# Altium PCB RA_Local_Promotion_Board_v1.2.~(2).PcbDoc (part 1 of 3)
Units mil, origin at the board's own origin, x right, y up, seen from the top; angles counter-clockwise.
Board outline 3390.27 x 5338.61 mil, 4 copper layers (Top Layer, Signal Layer 1, Signal Layer 2, Bottom Layer), stack 30.635 mil thick; 143 components, 181 nets, 726 pads, 394 vias.
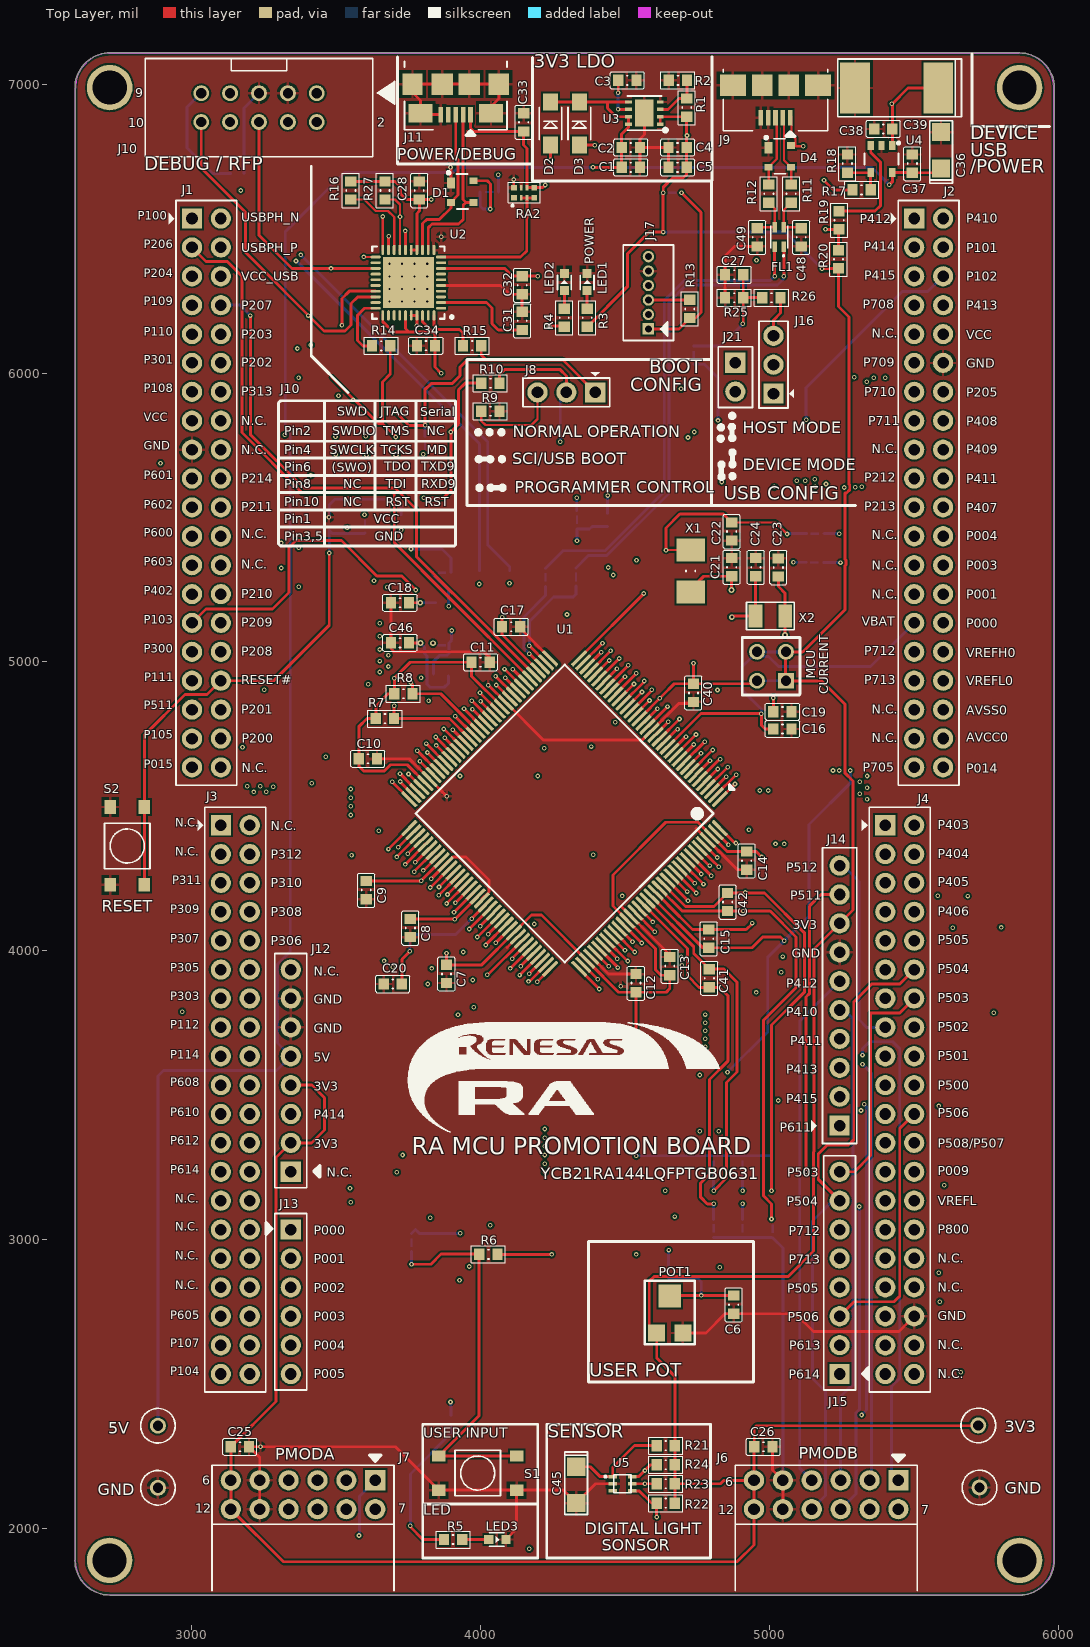
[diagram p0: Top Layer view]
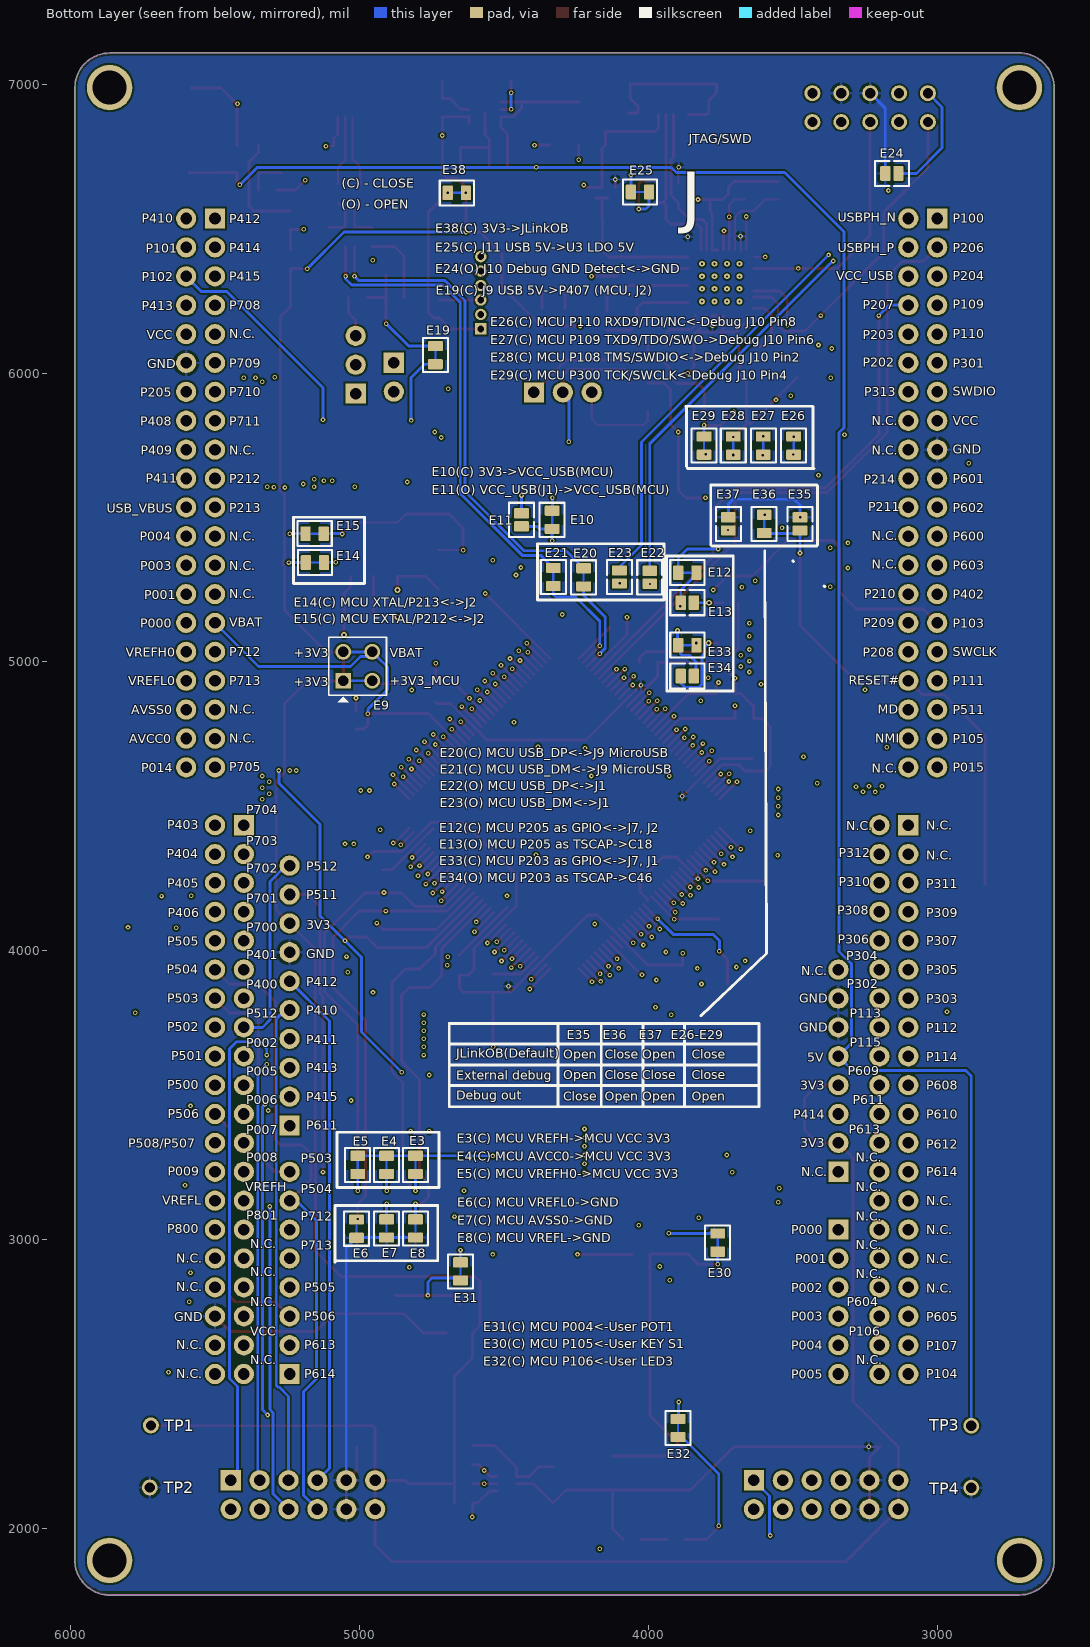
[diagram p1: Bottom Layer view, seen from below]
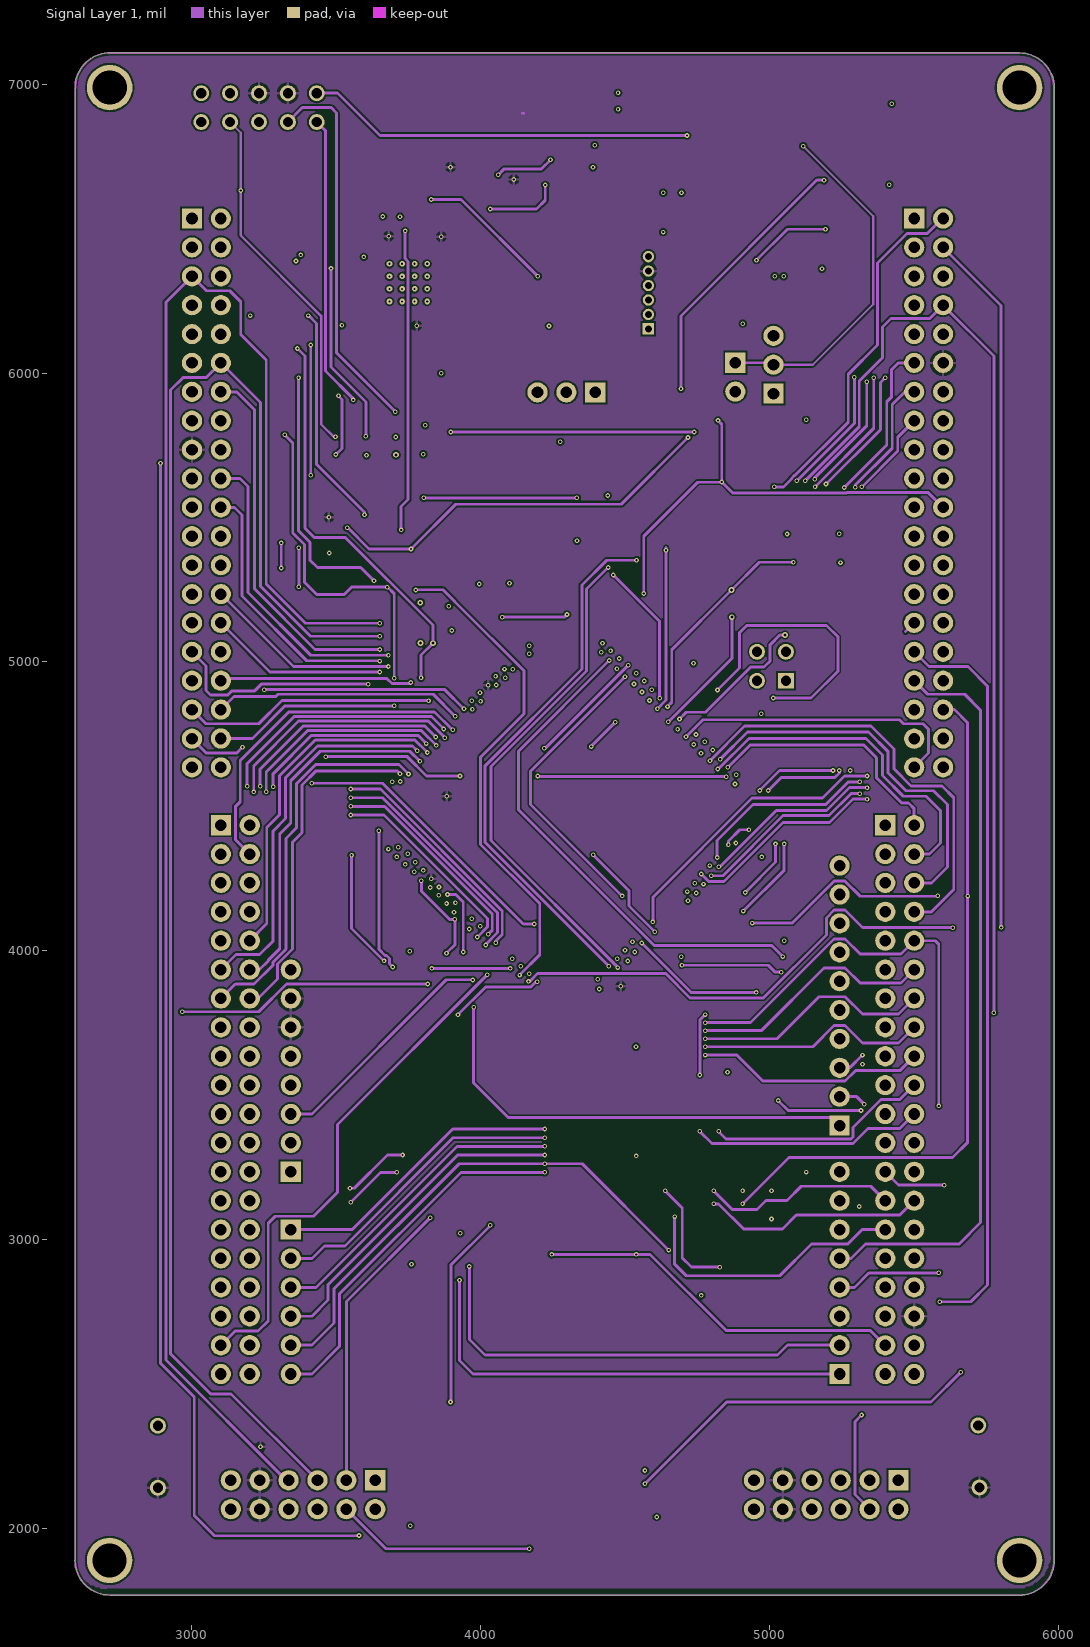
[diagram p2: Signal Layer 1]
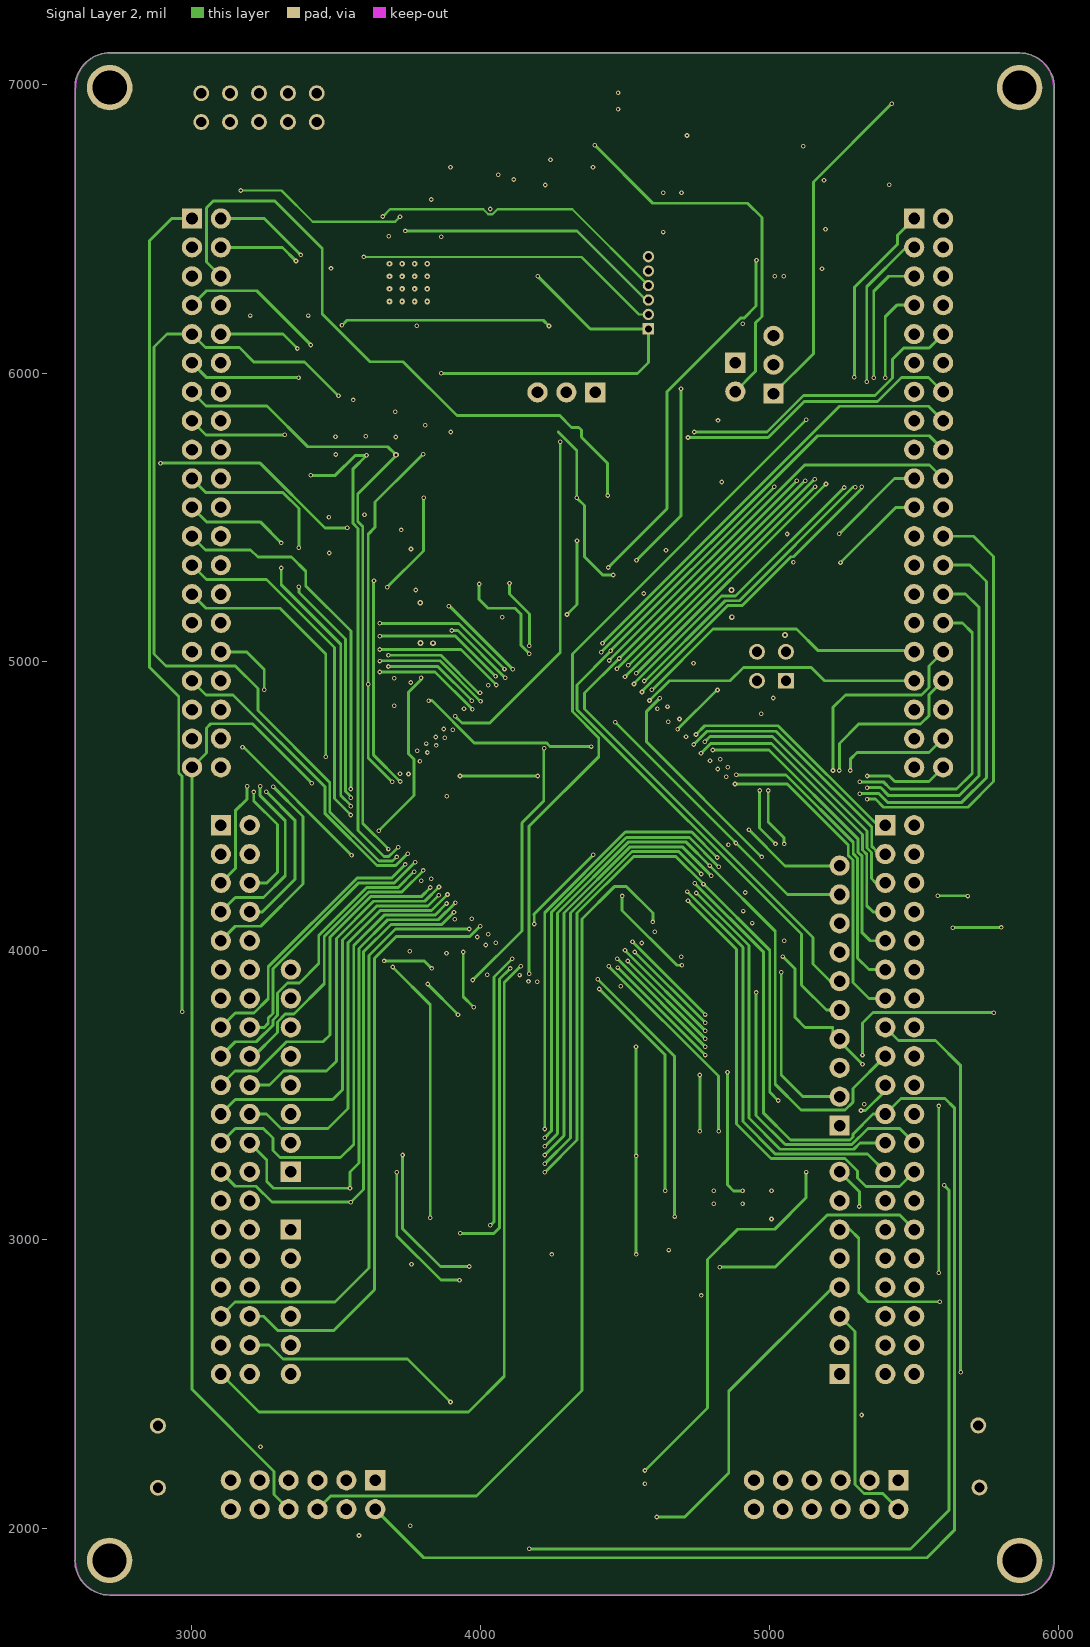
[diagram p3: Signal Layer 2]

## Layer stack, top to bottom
Top Solder: solder mask 0.4, Solder Resist, Dk 3.5
Top Layer: signal copper 1.4
Dielectric1: core 10, FR-4, Dk 4.2
Signal Layer 1: signal copper 1.4173
Dielectric2: prepreg 5, Dk 4.2
Signal Layer 2: signal copper 1.4173
Dielectric3: core 10, Dk 4.2
Bottom Layer: signal copper 1.4
Bottom Solder: solder mask 0.4, Solder Resist, Dk 3.5

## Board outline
2594.72,1889.76 cw(c2596.7,1889.76) 2595.1,1890.94 2595.1,6995.09 cw(c2597.09,6995.09) 2595.36,6996.07 cw(c2715.2,6988.19) 2707.32,7108.02 cw(c2708.3,7106.3) 2708.3,7108.28 5864.8,7108.28 cw(c5864.8,6988.19) 5984.9,6988.69 cw(c5983,6988.1) 5984.98,6988.1 5984.98,1881 cw(c5983,1881) 5984.56,1879.77 cw(c5864.88,1889.76) 5874.87,1770.09 cw(c5873.65,1771.65) 5873.65,1769.67 2714.81,1769.67 cw(c2714.81,1771.65) 2714.79,1769.67 cw(c2714.81,1889.76)

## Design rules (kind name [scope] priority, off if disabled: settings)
Clearance Clearance_1 [All] p1: gap=6
Clearance [All] p2: gap=10
FabricationTestpoint [(IsPad And (OnTopLayer Or OnBottomLayer))] p1: side=3 testpointundercomponent=TRUE minsize=40 maxsize=100 preferedsize=60 minholesize=0 maxholesize=40 preferedholesize=32 testpointgrid=1 allowsidetop=TRUE allowsidebottom=TRUE usegrid=TRUE gridtolerance=0.01
PolygonConnect [All] p1: connectstyle=Relief reliefconductorwidth=10 reliefentries=4 polygonreliefangle="90 Angle" airgapwidth=10
RoutingVias [All] p1: holewidth=28 width=50 viastyle="Through Hole" minholewidth=28 minwidth=50 maxholewidth=28 maxwidth=50
SolderMaskExpansion [All] p1: expansion=4
Width Width_1 [All] p1: maxlimit=20 minlimit=6 preferedwidth=10
Width [All] p2: maxlimit=10 minlimit=10 preferedwidth=10
29 further rules are at their usual default settings.

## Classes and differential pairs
component class RA_Local_Promotion_Board_5: C41 C42 J1 J2 J3 J4 J12 J13 J14 J15
component class RA_Local_Promotion_Board_4: C28 C31 C32 C33 C34 D1 E24 E25 E26 E27 E28 E29 E35 E36 E37 J8 J10 J11 J17 J20 R9 R10 R13 R14 R15 R16 R27 RA2 U2
component class RA_Local_Promotion_Board_3: C25 C26 C27 C36 C37 C38 C39 C45 C48 C49 D4 E19 FL1 J6 J7 J9 J16 J21 R11 R12 R17 R18 R19 R20 R21 R22 R23 R24 R25 R26 S2 U4 U5
component class RA_Local_Promotion_Board_1: 3V3 C7 C8 C9 C10 C11 C12 C13 C14 C15 C16 C17 C18 C19 C20 C23 C24 C40 C46 E3 E4 E5 E6 E7 E8 E9 E10 E11 E12 E13 E14 E15 E20 E21 E22 E23 E33 E34 GND R7 R8 U1 X2
component class RA_Local_Promotion_Board_2: 5V C1 C2 C3 C4 C5 C6 D2 D3 E30 E31 E32 E38 LED1 LED2 LED3 POT1 "POWER FOR U2" R1 R2 R3 R4 R5 R6 S1 U3

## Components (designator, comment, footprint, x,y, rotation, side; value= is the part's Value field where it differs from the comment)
3V3 "Test Point" "TP A - Red" 5722,2357 r0 top (schematic designator TP1)
5V "Test Point" "TP A - Red" 2882,2356 r0 top (schematic designator TP3)
C1 "0.1uF" CAPC0603-01 4519,6712 r180 top
C2 "10uF" CAPC0603-01 4519,6781 r180 top
C3 "10nF" CAPC0603-01 4507,7013 r180 top
C4 "10nF" CAPC0603-01 4681,6781 r0 top
C5 "10uF" CAPC0603-01 4681,6712 r0 top
C6 "0.1uF" CAPC0603-01 4875,2775 r90 top
C7 "4.7uF" CAPC0603-01 3881,3920 r90 top
C8 "0.1uF" CAPC0603-01 3756,4079 r90 top
C9 "0.1uF" CAPC0603-01 3603,4210 r90 top
C10 "0.1uF" CAPC0603-01 3609,4665 r0 top
C11 "0.1uF" CAPC0603-01 3999,4999 r0 top
C12 "0.1uF" CAPC0603-01 4537,3888 r90 top
C13 "0.1uF" CAPC0603-01 4654,3947 r90 top
C14 "0.1uF" CAPC0603-01 4920,4312 r90 top
C15 "0.1uF" CAPC0603-01 4789,4042 r90 top
C16 "0.1uF" CAPC0603-01 5044,4768 r0 top
C17 "0.1uF" CAPC0603-01 4105,5122 r0 top
C18 "0.1uF" CAPC0603-01 3720,5205 r180 top
C19 "0.1uF" CAPC0603-01 5044,4828 r180 top
C20 "0.1uF" CAPC0603-01 3695,3885 r0 top
C21 "10pF" CAPC0603-01 4868,5328 r270 top
C22 "10pF" CAPC0603-01 4868,5451.5 r90 top
C23 "12pF" CAPC0603-01 5030,5327 r270 top
C24 "12pF" CAPC0603-01 4952,5328 r270 top
C25 "4.7uF" CAPC0603-01 3166,2283 r180 top
C26 "4.7uF" CAPC0603-01 4978,2283 r180 top
C27 "1uF" CAPC0603-01 4877,6340 r0 top
C28 "0.1uF" CAPC0603-01 3787,6632 r270 top
C31 "4.7uF" CAPC0603-01 4143,6181 r270 top
C32 "0.1uF" CAPC0603-01 4143,6304 r90 top
C33 "0.1uF" CAPC0603-01 4148,6868 r270 top
C34 "0.1uF" CAPC0603-01 3810,6095 r0 top
C36 "10uF" "ELEC A" 5593,6771 r270 top
C37 "0.1uF" CAPC0603-01 5494,6725 r270 top
C38 "0.1uF" CAPC0603-01 5393,6845 r0 top
C39 "150uF" CAPSC2917(7343) 5439,6987 r180 top
C40 "0.1uF" CAPC0603-01 4736,4893 r270 top
C41 "0.1uF" CAPC0603-01 4791,3905 r270 top
C42 "0.1uF" CAPC0603-01 4854,4169 r270 top
C45 "1uF" "C1206 (3216)" 4330,2151 r90 top
C46 "0.1uF" CAPC0603-01 3720,5066 r180 top
C48 "470pF" CAPC0603-01 5109,6470 r90 top
C49 "470pF" CAPC0603-01 4956.61,6470 r90 top
D1 "AP2151WG-7" SOT-143B 3935.75,6628.28 r270 top
D2 "MBR140SFT1G" ONSEMI_SOD-123LF 4241,6864 r90 top
D3 "MBR140SFT1G" ONSEMI_SOD-123LF 4341,6864 r90 top
D4 "AP2151WG-7" SOT-143B 5035,6750 r270 top
E3 "Jumper Trace Cut" E_PadsTraceCut0805 4806,3259 r0 bottom
E4 "Jumper Trace Cut" E_PadsTraceCut0805 4906,3259 r0 bottom
E5 "Jumper Trace Cut" E_PadsTraceCut0805 5006,3259 r0 bottom
E6 "Jumper Trace Cut" E_PadsTraceCut0805 5010,3038 r0 bottom
E7 "Jumper Trace Cut" E_PadsTraceCut0805 4906,3039 r0 bottom
E8 "Jumper Trace Cut" E_PadsTraceCut0805 4806,3039 r0 bottom
E9 "Dual Jumper Trace Cut" "CON-4A - B" 5006,4985 r180 bottom
E10 "Jumper Trace Cut" E_PadsTraceCut0805 4333,5492 r0 bottom
E11 "Jumper Solder Bridging" E_PadsSplit0805 4439,5492 r0 bottom
E12 "Jumper Trace Cut" E_PadsTraceCut0805 3865,5309.02 r270 bottom
E13 "Jumper Solder Bridging" E_PadsSplit0805 3865,5205 r270 bottom
E14 "Jumper Trace Cut" E_PadsTraceCut0805 5154,5344 r90 bottom
E15 "Jumper Trace Cut" E_PadsTraceCut0805 5155,5444 r90 bottom
E19 "Jumper Trace Cut" E_PadsTraceCut0805 4737,6062 r0 bottom
E20 "Jumper Trace Cut" E_PadsTraceCut0805 4224,5293 r180 bottom
E21 "Jumper Trace Cut" E_PadsTraceCut0805 4329,5294 r180 bottom
E22 "Jumper Solder Bridging" E_PadsSplit0805 3995,5293 r0 bottom
E23 "Jumper Solder Bridging" E_PadsSplit0805 4100,5294 r0 bottom
E24 "Jumper Solder Bridging" E_PadsSplit0805 3157,6691 r90 bottom
E25 "Jumper Trace Cut" E_PadsTraceCut0805 4029,6627 r270 bottom
E26 "Jumper Trace Cut" E_PadsTraceCut0805 3497,5749 r0 bottom
E27 "Jumper Trace Cut" E_PadsTraceCut0805 3602,5749 r0 bottom
E28 "Jumper Trace Cut" E_PadsTraceCut0805 3706,5749 r0 bottom
E29 "Jumper Trace Cut" E_PadsTraceCut0805 3807,5749 r0 bottom
E30 "Jumper Trace Cut" E_PadsTraceCut0805 3760,2990 r180 bottom
E31 "Jumper Trace Cut" E_PadsTraceCut0805 4650,2890 r180 bottom
E32 "Jumper Trace Cut" E_PadsTraceCut0805 3897,2348 r180 bottom
E33 "Jumper Trace Cut" E_PadsTraceCut0805 3865,5058 r90 bottom
E34 "Jumper Solder Bridging" E_PadsSplit0805 3865,4951 r90 bottom
E35 "Jumper Solder Bridging" E_PadsSplit0805 3475,5478 r180 bottom
E36 "Jumper Trace Cut" E_PadsTraceCut0805 3599,5478 r0 bottom
E37 "Jumper Solder Bridging" E_PadsSplit0805 3723,5478 r180 bottom
E38 "Jumper Trace Cut" E_PadsTraceCut0805 4663,6624 r270 bottom
FL1 "90R" CKS4B20X12X 5033,6470.79 r90 top
GND "Test Point" "TP A - BLK" 5726,2142 r0 top (schematic designator TP2)
GND "Test Point" "TP A - BLK" 2882,2141 r0 top (schematic designator TP4)
J1 "2x20" SULLINS_PPPC202LFBN-RC 3050,5585 r270 top
J2 "2x20" SULLINS_PPPC202LFBN-RC 5550,5585 r270 top
J3 "2x20" SULLINS_PPPC202LFBN-RC 3150,3485 r270 top
J4 "2x20" SULLINS_PPPC202LFBN-RC 5450,3485 r270 top
J6 "PMOD" SULLINS_PPTC062LFBN-RC-PMOD 5195.51,2117 r180 top
J7 "PMOD" SULLINS_PPTC062LFBN-RC-PMOD 3384.49,2117 r180 top
J8 "2.54mm 1x3" FCI_6800-x03 4296,5933 r180 top
J9 "UBAF-0608" FCI_10104111-0001LF 5020,6996 r180 top
J10 "1.27mm 2x5" "CON-10 C" 3232,6919 r180 top
J11 "UBAF-0608" USBSB5_6 3913,7000 r180 top
J12 "2.54mm 1x8" FCI_77311-818-08LF 3342,3585 r90 top
J13 "2.54mm 1x6" FCI_77311-818-06LF 3342,2785 r270 top
J14 "2.54mm 1x10" FCI_77311-818-10LF 5242,3845 r90 top
J15 "2.54mm 1x8" FCI_77311-818-08LF 5242,2885 r90 top
J16 "2.54mm 1x3" FCI_6800-x03 5013,6029 r90 top
J17 "TC-2030" "JC-6pin-1.27 - duplicate" 4580,6278 r180 top
J21 "2.54mm 1x2" FCI_67966-X02 4881,5986 r180 top
LED1 "LED Green" LED_0603-GRN 4368,6315.47 r90 top
LED2 "LED Red" LED_0603-RED 4289,6315.47 r90 top
LED3 "LED Red" LED_0603-RED 4057,1962 r0 top
POT1 "10K" "3X3 REGISTER" 4654,2740 r0 top
R1 "56K" RESC0603-01 4713,6919 r270 top
R2 "10K" RESC0603-01 4682,7013 r0 top
R3 "470R" RESC0603-01 4368,6191.47 r90 top
R4 "1K5" RESC0603-01 4289,6191.47 r90 top
R5 "470R" RESC0603-01 3904,1962 r0 top
R6 "47K" RESC0603-01 4026,2949 r0 top
R7 "10K" RESC0603-01 3668,4804 r180 top
R8 "10K" RESC0603-01 3732,4890 r180 top
R9 "1K5" RESC0603-01 4033,5868 r180 top
R10 "10K" RESC0603-01 4033,5965 r180 top
R11 "0R" RESC0603-01 5074,6621 r90 top
R12 "0R" RESC0603-01 4997,6621 r90 top
R13 "4K7" RESC0603-01 4723,6222 r270 top
R14 "150R" RESC0603-01 3655,6094 r180 top
R15 "150R" RESC0603-01 3970,6095 r180 top
R16 "4K7" RESC0603-01 3550,6632 r270 top
R17 "0R" RESC0603-01 5318,6634 r0 top
R18 "100K" RESC0603-01 5269,6725 r270 top
R19 "0R" RESC0603-01 5240,6529 r270 top
R20 "10K" RESC0603-01 5238,6394 r270 top
R21 "100R" RESC0603-01 4640,2287 r180 top
R22 "4K7" RESC0603-01 4640,2088 r0 top
R23 "4K7" RESC0603-01 4640,2155 r0 top
R24 "4K7" RESC0603-01 4640,2221 r0 top
R25 "30K" RESC0603-01 4877,6261 r0 top
R26 "15K" RESC0603-01 5006,6261 r0 top
R27 "4K7" RESC0603-01 3668,6632 r270 top
RA2 "10K" RESCAF0804 4149.84,6624.28 r0 top
S1 "Switch 4.5x4.5mm" "KEY A (4.5 X 4.5)" 3989,2192 r0 top
S2 "Switch 4.5x4.5mm" "KEY A (4.5 X 4.5)" 2776,4363 r270 top
U1 "RA6M2" RENESAS_PLQP0144KA-B_N 4290,4475 r225 top
U2 "S124-QFN40" RENESAS_P-HWQFN40-6x6-0.50 3749,6313 r180 top
U3 "ISL80510IRAJZ" "DFN8 (3x3) Pitch 0.65" 4566,6900 r90 top
U4 "AP2151WG-7" SOT25 5387,6741 r270 top
U5 "ISL29035" 6-ODFN-29035 4490,2155 r0 top
X1 "24MHz" OSC_5032 4726,5314.96 r90 top
X2 "32.769KHz" ABRACON_ABS07 5002,5159 r180 top

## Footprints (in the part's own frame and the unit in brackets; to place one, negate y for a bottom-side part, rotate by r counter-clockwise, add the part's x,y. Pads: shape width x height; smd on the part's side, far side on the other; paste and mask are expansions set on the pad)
"3X3 REGISTER" [mm]
  rect 1.5x1.5 smd: 1(-1.15,-1.6) 3(1.15,-1.6)
  rect 2x2 smd: 2(0,1.65)
  silkscreen extent -2.21,-2.6 2.2,3, body extent -1.75,-1.67 1.65,1.93, height 2
6-ODFN-29035 [mm] "6Ld  1.5X1.6mm"
  rect 0.75x0.3 smd: 1(-0.85,0.625) 2(-0.85,0) 3(-0.85,-0.625) 4(0.85,-0.625) 5(0.85,0) 6(0.85,0.625)
  silkscreen extent -1.58,-0.8 0.75,0.8, body extent -0.8,-0.75 0.8,0.75, height 0.55
ABRACON_ABS07 [mm] "ABRACON 32.768KHz Crystal ABS07"
  rect 1.2x2 smd: 1(-1.3,0) 2(1.3,0)
  silkscreen extent -2.1,-1.2 2.1,1.2, body extent -1.61,-0.75 1.61,0.77, height 0.91
"C1206 (3216)" [mm]
  rect 1.6x1.6 smd: 1(1.6,0) 2(-1.6,0)
  silkscreen extent -2.6,-1 2.9,1, body extent -2.4,-0.89 2.4,0.91, height 1.8
CAPC0603-01 [mm] "Chip Capacitor, Body 1.6x0.8mm, Height 0.55mm, IPC Medium Density"
  rect 0.9x1 smd: 1(-0.8,0) 2(0.8,0)
  silkscreen extent -1.5,-0.75 1.5,0.75, body extent -0.87,-0.48 0.88,0.47, height 0.55
CAPSC2917(7343) [mm] "Tant Capacitor; Body 6.00mm x 3.20mm"
  rect 2.6x4.5 smd: 1(-3.65,0) 2(3.65,0)
  silkscreen extent -5.71,-2.54 5.16,2.54, body extent -3.88,-2.15 3.88,2.15, height 2
CKS4B20X12X [mil] "CKS4B20X12X"
  rect 36x16 smd: 1(-33.75,-15.87) 2(33.75,-15.87) 3(33.75,15.87) 4(-33.75,15.87)
  silkscreen extent -68,-30 39,30, body extent -39,-24 39,24, height 47
"CON-4A - B" [mm]
  rect 1.4x1.4 hole 0.9: 1(-1.27,-1.27)
  round 1.4 hole 0.9: 2(-1.27,1.27) 3(1.27,-1.27) 4(1.27,1.27)
  Top Layer lines w0.254: 1.27,-1.27 -1.27,-1.27 ; 1.27,1.27 0.291,1.27 -0.533,1.27 -1.27,1.27
  silkscreen extent -2.54,-3.17 2.54,2.54
"CON-10 C" [mm]
  round 1.4 hole 0.9: 1(-5.08,-1.27) 2(-5.08,1.27) 3(-2.54,-1.27) 4(-2.54,1.27) 5(0,-1.27) 6(0,1.27) 7(2.54,-1.27) 8(2.54,1.27) 9(5.08,-1.27) 10(5.08,1.27)
  silkscreen extent -11.91,-4.32 10,4.32, body extent -10.16,-4.55 10.16,4.55, height 9
"DFN8 (3x3) Pitch 0.65" [mm] "DFN8, 8-Leads, Body 3x3mm, Pitch 0.65mm"
  rect 0.3x0.6 smd: 1(-0.975,-1.4) 2(-0.325,-1.4) 3(0.325,-1.4) 4(0.975,-1.4) 5(0.975,1.4) 6(0.325,1.4) 7(-0.325,1.4) 8(-0.975,1.4)
  rect 2.38x1.64 smd: PAD(0,0)
  silkscreen extent -1.6,-1.95 1.5,1.5, body extent -1.49,-1.5 1.5,1.5, height 0.9
E_PadsSplit0805 [mm] "0805 size Pads Only on PCB with 10mil space to allow separation solder bridging or 0402-0805 resistor mount"
  rrect20% 1.3x0.9 smd: 1(0,0.575) 2(0,-0.575)
  Top Layer pour cut-out: -1,0.2 1,0.2 1,-0.2 -1,-0.2
  silkscreen extent -1.1,-1.5 1.1,1.5
E_PadsTraceCut0805 [mm] "0805-size Pads only on PCB with an 8mil wide cuttable trace to allow separation"
  rrect20% 1.3x0.9 smd: 1(0,0.8) 2(0,-0.8)
  Top Layer region: -0.1,0.375 0.1,0.375 0.1,-0.375 -0.1,-0.375
  Top Layer pour cut-out: -1,0.425 1,0.425 1,-0.425 -1,-0.425
  silkscreen extent -1.1,-1.5 1.1,1.5
"ELEC A" [mm]
  rect 1.6x1.6 smd: 1(1.6,0) 2(-1.6,0)
  silkscreen extent -2.6,-1 2.9,1, body extent -1.6,-0.87 1.6,0.87, height 1.61
FCI_6800-x03 [mil] "FCI 1x3 0.1\" straight male header"
  rect 70x70 hole 40: 1(-100,0)
  round 70 hole 40: 2(0,0) 3(100,0)
  silkscreen extent -150,-70 150,50, body extent -150,-50 150,50, height 362
FCI_67966-X02 [mil] "FCI Header Male 0.1\" pitch 2pos 1x2"
  rect 70x70 hole 40: 1(0,-50)
  round 70 hole 40: 2(0,50)
  silkscreen extent -59,-105 59,105, body extent -50,-100 50,100, height 332
FCI_77311-818-06LF [mil] "FCI Header Male 0.1\" pitch 6pos"
  rect 70x70 hole 40: 1(-250,0)
  round 70 hole 40: 2(-150,0) 3(-50,0) 4(50,0) 5(150,0) 6(250,0)
  silkscreen extent -306,-85 306,55, body extent -300,-49 300,49, height 323
FCI_77311-818-08LF [mil] "FCI Header Male 0.1\" pitch 8pos"
  rect 70x70 hole 40: 1(-350,0)
  round 70 hole 40: 2(-250,0) 3(-150,0) 4(-50,0) 5(50,0) 6(150,0) 7(250,0) 8(350,0)
  silkscreen extent -406,-100 406,55, body extent -400,-45 400,55, height 362
FCI_77311-818-10LF [mil] "FCI Header Male 0.1\" pitch 10pos"
  rect 70x70 hole 40: 1(-450,0)
  round 70 hole 40: 2(-350,0) 3(-250,0) 4(-150,0) 5(-50,0) 6(50,0) 7(150,0) 8(250,0) 9(350,0) 10(450,0)
  silkscreen extent -512,-59 512,98, body extent -500,-55 500,45, height 362
FCI_10104111-0001LF [mm] "FCI USB Micro AB Full SMT"
  rect 0.4x1.4 smd: 1(-1.3,2.85) 2(-0.65,2.85) 3(0,2.85) 4(0.65,2.85) 5(1.3,2.85)
  rect 2.3x1.9 smd: C1(-3.75,0) C4(3.75,0)
  rect 1.8x1.9 smd: C2(-1.15,0) C3(1.15,0)
  silkscreen extent -4.6,-1.43 4.6,4.47, body extent -4.4,-2.79 4.4,2.84, height 2.79
"JC-6pin-1.27 - duplicate" [mm]
  rect 1x1 hole 0.6: 1(0,3.175)
  round 1 hole 0.6: 2(0,1.905) 3(0,0.635) 4(0,-0.635) 5(0,-1.905) 6(0,-3.175)
  silkscreen extent -2.2,-4.2 2.2,4.2
"KEY A (4.5 X 4.5)" [mm]
  rect 1.2x1 smd: 1(-3.425,1.5) 2(-3.425,-1.5) 3(3.425,-1.5) 4(3.425,1.5)
  silkscreen extent -2,-2 2,2, body extent -3.75,-2.25 3.75,2.25, height 3.7
LED_0603-GRN [mm] "SMT LED 0603 Green"
  rect 0.8x0.8 smd: A(-0.75,0) K(0.75,0)
  silkscreen extent -0.7,-0.6 0.6,0.6, body extent -0.8,-0.4 0.8,0.4, height 0.6
LED_0603-RED [mm] "SMT LED 0603 Red"
  rect 0.8x0.8 smd: A(-0.75,0) K(0.75,0)
  silkscreen extent -0.7,-0.6 0.6,0.6, body extent -0.8,-0.4 0.8,0.4, height 0.6
ONSEMI_SOD-123LF [mm] "OnSemi Schottky Power Rectifier"
  rect 1.5x1.3 smd: A(-1.9,0) K(1.9,0)
  silkscreen extent -1.4,-1 1.4,1, body extent -1.93,-0.85 1.92,0.85, height 1.44
OSC_5032 [mm] "Chip Capacitor, Body 1.6x0.8mm, Height 0.55mm, IPC Medium Density"
  rect 2x2.5 smd: 1(-1.85,0) 2(1.85,0)
  silkscreen extent -0.05,-0.4 0.05,0.4, body extent -2.5,-1.6 2.5,1.6, height 1.3
RENESAS_P-HWQFN40-6x6-0.50 [mm] "Renesas QFN, 40-Leads, Body 6.00x6.00mm, Pitch 0.50mm, Thermal Pad 4.50x4.50mm, IPC Medium Density"
  oval 0.9x0.25 smd: 1(-2.875,2.25) 2(-2.875,1.75) 3(-2.875,1.25) 4(-2.875,0.75) 5(-2.875,0.25) 6(-2.875,-0.25) 7(-2.875,-0.75) 8(-2.875,-1.25) 9(-2.875,-1.75) 10(-2.875,-2.25) 21(2.875,-2.25) 22(2.875,-1.75) 23(2.875,-1.25) 24(2.875,-0.75) 25(2.875,-0.25) 26(2.875,0.25) 27(2.875,0.75) 28(2.875,1.25) 29(2.875,1.75) 30(2.875,2.25)
  oval 0.25x0.9 smd: 11(-2.25,-2.875) 12(-1.75,-2.875) 13(-1.25,-2.875) 14(-0.75,-2.875) 15(-0.25,-2.875) 16(0.25,-2.875) 17(0.75,-2.875) 18(1.25,-2.875) 19(1.75,-2.875) 20(2.25,-2.875) 31(2.25,2.875) 32(1.75,2.875) 33(1.25,2.875) 34(0.75,2.875) 35(0.25,2.875) 36(-0.25,2.875) 37(-0.75,2.875) 38(-1.25,2.875) 39(-1.75,2.875) 40(-2.25,2.875)
  rect 4.5x4.5 smd: 41(0,0)
  silkscreen extent -3.95,-3.18 3.18,3.18, body extent -3.03,-3.03 3.03,3.03, height 0.8
RENESAS_PLQP0144KA-B_N [mm] "Shrink QFP, 144-Leads, Body 20x20mm, Pitch 0.5mm, IPC Medium Density"
  rrect50% 1.8x0.3 smd: 1(-10.55,8.75) 2(-10.55,8.25) 3(-10.55,7.75) 4(-10.55,7.25) 5(-10.55,6.75) 6(-10.55,6.25) 7(-10.55,5.75) 8(-10.55,5.25) 9(-10.55,4.75) 10(-10.55,4.25) 11(-10.55,3.75) 12(-10.55,3.25) 13(-10.55,2.75) 14(-10.55,2.25) 15(-10.55,1.75) 16(-10.55,1.25) 17(-10.55,0.75) 18(-10.55,0.25) 19(-10.55,-0.25) 20(-10.55,-0.75) 21(-10.55,-1.25) 22(-10.55,-1.75) 23(-10.55,-2.25) 24(-10.55,-2.75) 25(-10.55,-3.25) 26(-10.55,-3.75) 27(-10.55,-4.25) 28(-10.55,-4.75) 29(-10.55,-5.25) 30(-10.55,-5.75) 31(-10.55,-6.25) 32(-10.55,-6.75) 33(-10.55,-7.25) 34(-10.55,-7.75) 35(-10.55,-8.25) 36(-10.55,-8.75) 73(10.55,-8.75) 74(10.55,-8.25) 75(10.55,-7.75) 76(10.55,-7.25) 77(10.55,-6.75) 78(10.55,-6.25) 79(10.55,-5.75) 80(10.55,-5.25) 81(10.55,-4.75) 82(10.55,-4.25) 83(10.55,-3.75) 84(10.55,-3.25) 85(10.55,-2.75) 86(10.55,-2.25) 87(10.55,-1.75) 88(10.55,-1.25) 89(10.55,-0.75) 90(10.55,-0.25) 91(10.55,0.25) 92(10.55,0.75) 93(10.55,1.25) 94(10.55,1.75) 95(10.55,2.25) 96(10.55,2.75) 97(10.55,3.25) 98(10.55,3.75) 99(10.55,4.25) 100(10.55,4.75) 101(10.55,5.25) 102(10.55,5.75) 103(10.55,6.25) 104(10.55,6.75) 105(10.55,7.25) 106(10.55,7.75) 107(10.55,8.25) 108(10.55,8.75)
  rrect50% 0.3x1.8 smd: 37(-8.75,-10.55) 38(-8.25,-10.55) 39(-7.75,-10.55) 40(-7.25,-10.55) 41(-6.75,-10.55) 42(-6.25,-10.55) 43(-5.75,-10.55) 44(-5.25,-10.55) 45(-4.75,-10.55) 46(-4.25,-10.55) 47(-3.75,-10.55) 48(-3.25,-10.55) 49(-2.75,-10.55) 50(-2.25,-10.55) 51(-1.75,-10.55) 52(-1.25,-10.55) 53(-0.75,-10.55) 54(-0.25,-10.55) 55(0.25,-10.55) 56(0.75,-10.55) 57(1.25,-10.55) 58(1.75,-10.55) 59(2.25,-10.55) 60(2.75,-10.55) 61(3.25,-10.55) 62(3.75,-10.55) 63(4.25,-10.55) 64(4.75,-10.55) 65(5.25,-10.55) 66(5.75,-10.55) 67(6.25,-10.55) 68(6.75,-10.55) 69(7.25,-10.55) 70(7.75,-10.55) 71(8.25,-10.55) 72(8.75,-10.55) 109(8.75,10.55) 110(8.25,10.55) 111(7.75,10.55) 112(7.25,10.55) 113(6.75,10.55) 114(6.25,10.55) 115(5.75,10.55) 116(5.25,10.55) 117(4.75,10.55) 118(4.25,10.55) 119(3.75,10.55) 120(3.25,10.55) 121(2.75,10.55) 122(2.25,10.55) 123(1.75,10.55) 124(1.25,10.55) 125(0.75,10.55) 126(0.25,10.55) 127(-0.25,10.55) 128(-0.75,10.55) 129(-1.25,10.55) 130(-1.75,10.55) 131(-2.25,10.55) 132(-2.75,10.55) 133(-3.25,10.55) 134(-3.75,10.55) 135(-4.25,10.55) 136(-4.75,10.55) 137(-5.25,10.55) 138(-5.75,10.55) 139(-6.25,10.55) 140(-6.75,10.55) 141(-7.25,10.55) 142(-7.75,10.55) 143(-8.25,10.55) 144(-8.75,10.55)
  Top Layer pour cut-out: 9.1,11.6 9.1,9.5 -9.1,9.5 -9.1,11.6
  Top Layer pour cut-out: 11.6,-9.1 9.5,-9.1 9.5,9.1 11.6,9.1
  Top Layer pour cut-out: -9.1,-11.6 -9.1,-9.5 9.1,-9.5 9.1,-11.6
  Top Layer pour cut-out: -11.6,9.1 -9.5,9.1 -9.5,-9.1 -11.6,-9.1
  silkscreen extent -12.05,-9.25 9.25,9.25, body extent -11,-10.95 11,11.05, height 1.64
RESC0603-01 [mm] "Chip Resistor, Body 1.6x0.8mm, IPC Medium Density"
  rect 0.9x1 smd: 1(-0.8,0) 2(0.8,0)
  silkscreen extent -1.5,-0.75 1.5,0.75, body extent -0.85,-0.47 0.85,0.47, height 0.6
RESCAF0804 [mm] "Chip Resistor Array 0804 4 x 0402"
  rect 0.525x0.5 smd: 1(-0.887,-0.45) 4(0.887,-0.45) 5(0.887,0.45) 8(-0.887,0.45)
  rect 0.25x0.5 smd: 2(-0.25,-0.45) 3(0.25,-0.45) 6(0.25,0.45) 7(-0.25,0.45)
  silkscreen extent -1.4,-1.22 1.4,0.9, body extent -1,-0.5 1,0.5, height 0.36
SOT25 [mm] "SOT25, 5-Leads, Body 3x3.1mm, Pitch 0.95mm"
  rect 0.8x0.55 smd: 1(-1.2,0.95) 2(-1.2,0) 3(-1.2,-0.95) 4(1.2,-0.95) 5(1.2,0.95)
  silkscreen extent -1.5,-1.5 0.5,1.6, body extent -1.17,-1.5 1.22,1.5, height 1.1
SOT-143B [mm] "SOT-143B, 4-Leads"
  rect 1x0.7 smd: 1(-0.75,-1)
  rect 0.6x0.7 smd: 2(0.95,-1) 3(0.95,1) 4(-0.95,1)
  silkscreen extent -1.77,-1.32 1.53,0.5, body extent -1.46,-1.21 1.46,1.21, height 1
SULLINS_PPPC202LFBN-RC [mil] "SULLINS Header Female 2x20 2.54mm Pitch"
  rect 70x70 hole 40: 1(-950,-50)
  round 70 hole 40: 2(-950,50) 3(-850,-50) 4(-850,50) 5(-750,-50) 6(-750,50) 7(-650,-50) 8(-650,50) 9(-550,-50) 10(-550,50) 11(-450,-50) 12(-450,50) 13(-350,-50) 14(-350,50) 15(-250,-50) 16(-250,50) 17(-150,-50) 18(-150,50) 19(-50,-50) 20(-50,50) 21(50,-50) 22(50,50) 23(150,-50) 24(150,50) 25(250,-50) 26(250,50) 27(350,-50) 28(350,50) 29(450,-50) 30(450,50) 31(550,-50) 32(550,50) 33(650,-50) 34(650,50) 35(750,-50) 36(750,50) 37(850.79,-50) 38(850,50) 39(950,-50) 40(950,50)
  silkscreen extent -1012,-131 1012,105, body extent -995,-105 1005,95, height 420
SULLINS_PPTC062LFBN-RC-PMOD [mil] "SULLINS 0.1\" Female Header 12pos PMOD 2x6"
  rect 70x70 hole 40: 1(-250,-50)
  round 70 hole 40: 2(-150,-50) 3(-50,-50) 4(50,-50) 5(150,-50) 6(250,-50) 7(-250,50) 8(-150,50) 9(-50,50) 10(50,50) 11(150,50) 12(250,50)
  silkscreen extent -315,-136 315,102, body extent -305,-61 315,441, height 198
"TP A - BLK" [mm]
  round 1.4 hole 0.9: 1(0,0)
  silkscreen extent -1.52,-1.52 1.52,1.52, body extent -1.59,-1.58 1.59,1.58, height 8.13
"TP A - Red" [mm]
  round 1.4 hole 0.9: 1(0,0)
  silkscreen extent -1.52,-1.52 1.52,1.52, body extent -1.59,-1.58 1.59,1.58, height 8.13
USBSB5_6 [mm] "FCI USB Micro B Full SMT"
  rect 0.4x1.35 smd: 1(-1.3,2.675) 2(-0.65,2.675) 3(0,2.675) 4(0.65,2.675) 5(1.3,2.675)
  rect 2.1x1.6 smd: C1(-3.1,2.55) C2(3.1,2.55)
  rect 1.8x1.9 smd: C3(-3.8,0) C4(3.8,0)
  rect 1.9x1.9 smd: C3(-1.2,0) C4(1.2,0)
  silkscreen extent -4.5,-2 4.5,4.47, body extent -3.96,-2.76 3.96,2.9, height 2.77

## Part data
3V3 5V GND GND: library part "CON-Test Point"
C1 C6 C8 C9 C10 C11 C12 C13 C14 C15 C16 C17 C18 C19 C20 C28 C32 C33 C34 C37 C38 C40 C41 C42 C46: library part CAP-0603-0.1uF, "Ceramic Chip Capacitor 0603 0.1uF 50V"
C2 C5: library part CAP-0603-10uF, "Ceramic Chip Capacitor 0603 10uF 6.3V"
C3 C4: library part CAP-0603-10nF, "Ceramic Chip Capacitor 0603 10nF 50V"
C7 C25 C26 C31: library part CAP-0603-4.7uF, "Ceramic Chip Capacitor 0603 4.7uF 6.3V"
C21 C22: library part CAP-0603-10pF, "Ceramic Chip Capacitor 0603 10pF 50V"
C23 C24: library part CAP-0603-12pF, "Ceramic Chip Capacitor 0603 12pF 50V"
C27: library part CAP-0603-1uF, "Ceramic Chip Capacitor 0603 1uF 50V"
C36: library part CAP-1206-10uF, "Tantalum Capacitor 1206 10uF 16V"
C39: library part CAP-2917-150uF, "Tantalum Capacitor 2917 150uF 16V"
C45: library part CAP-1206-1uF, "Tantalum Capacitor 1uF 25V 20% 1206"
C48 C49: library part CAP-0603-470pF, "Ceramic Chip Capacitor 0603 470pF 50V"
D1 D4: library part DIO-PRTR5V0U2X, "IC PWR SWITCH P-CHAN 1:1 SOT25"
D2 D3: library part DIO-MBR140SFT1G, "OnSemi Schottky Power Rectifier 40V 1A"
E3 E4 E5 E6 E7 E8 E9 E10 E12 E14 E15 E19 E20 E21 E25 E26 E27 E28 E29 E30 E31 E32 E33 E36 E38: library part E_JmpTraceCut, "Pads on PCB with Trace Between for Cutting to isolate"
E11 E13 E22 E23 E24 E34 E35 E37: library part E_JmpSldrBridge, "Pads on PCB with Narrow Gap to allow Solder Bridging"
FL1: library part IND-SMD0805-LC, "Common Choke,90ohm@100MHz/20°C,±25%,330mA,0.35ohm,SMD0805"
J1 J2 J3 J4: library part "CON-2.54mm 2x20 Male", "Header Male 2.54mm 40pos 2x20"
J6 J7: library part "CON-2.54mm 2x6 Female", "Female Header 0.1\" pitch 2x6 Female"
J8 J16: library part "CON-2.54mm 1x3", "Header 0.1\" pitch 3pos 1x3"
J9 J11: library part USB-UBAF-0608, "Connector,MicroUSB B port,5 Position,Right Angle,Gold Flash 1u,black,SMD"
J10: library part "CON-1.27mm 2x5 MALE SMT", "Pin header,RA,male,1.27pitch,2X5p,3H,2.5MM,GF 10u,Getrid 8th pin,Dip"
J12 J15: library part "CON-2.54mm 1x8", "FCI Header 0.1\" pitch 8pos 1x8"
J13: library part "CON-2.54mm 1x6", "FCI Header 0.1\" pitch 6pos 1x6"
J14: library part "CON-2.54mm 1x10", "FCI Header 0.1\" pitch 10pos 1x10"
J17: library part CON-TC-2030, "Tag Connect TC-2030 PCB Pads 6 Pos 2x3"
J21: library part "CON-2.54mm 1x2", "FCI Header 0.1\" pitch 2pos 1x2"
LED1: library part LED-0603-Green, "Lite-On LED Green Clear 0603"
LED2 LED3: library part LED-0603-Red, "Lite-On LED Red Clear 0603"
POT1: library part POT-10K, "Bourns Single Turn Trimmer 10K"
R1: library part RES-0603-56K, "Chip Resistor Thick Film 0603 56K 1% 1/10W"
R2 R7 R8 R10 R20: library part RES-0603-10K, "Chip Resistor Thick Film 0603 10K 1% 1/10W"
R3 R5: library part RES-0603-470R, "Chip Resistor Thick Film 0603 470R 1% 1/10W"
R4 R9: library part RES-0603-1K5, "Chip Resistor Thick Film 0603 1K5 1% 1/10W"
R6: library part RES-0603-47K, "Chip Resistor Thick Film 0603 47K 1% 1/10W"
R11 R12 R17 R19: library part RES-0603-0R, "Chip Resistor Thick Film 0603 0R 1% 1/10W"
R13 R16 R22 R23 R24 R27: library part RES-0603-4K7, "Chip Resistor Thick Film 0603 4K7 1% 1/10W"
R14 R15: library part RES-0603-150R, "Chip Resistor Thick Film 0603 150R 1% 1/10W"
R18: library part RES-0603-100K, "Chip Resistor Thick Film 0603 100K 1% 1/10W"
R21: library part RES-0603-200R, "Chip Resistor Thick Film 0603 100R 1% 1/10W"
R25: library part RES-0603-30K, "Chip Resistor Thick Film 0603 30K 1% 1/10W"
R26: library part RES-0603-15K, "Chip Resistor Thick Film 0603 15K 1% 1/10W"
RA2: library part RES-0804-10K, "Chip Resistor Array 0804 10K 5% 1/16W 4 x 0402"
S1 S2: library part SWT-4.5x4.5mm, "Push Button Switch 4.5 x 4.5mm 3.8mm High"
U1: library part ICN-RA6M2-LQFP144, "Renesas RA6M2 ARM Cortex M4 120MHz MCU LQFP144"
U2: library part ICN-S124-QFN40, "Renesas S124 32-Bit 32MHz Cortex M0+ MCU QFN40"
U3: library part ICN-ISL80510, "IC REG LINEAR POS ADJ 1A 8-DFN（3x3）"
U4: library part ICN-AP2151WG-7, "IC PWR SWITCH P-CHAN 1:1 SOT25"
U5: library part ICN-ISL29035, "Integrated Digital Light Sensor  6 LD ODFN"
X1: library part "XTL-32.769KHz SMT", "Crystal 24MHz SMT"
X2: library part "XTL-32.769KHz SMT", "Crystal 32.769KHz 12.5pF SMT"

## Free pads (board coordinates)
  round 157.48 hole 118.11: ""(2714.8,1889.76) ""(2715.2,6988.19) ""(5864.8,6988.19) ""(5864.88,1889.76)

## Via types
v1: diameter 16, hole 8, Top Layer to Bottom Layer, 368 vias
v2: diameter 19.68, hole 7.87, Top Layer to Bottom Layer, 16 vias
v3: diameter 20, hole 10, Top Layer to Bottom Layer, 7 vias
v4: diameter 16, hole 8, Top Layer to Bottom Layer, tented both sides, 3 vias

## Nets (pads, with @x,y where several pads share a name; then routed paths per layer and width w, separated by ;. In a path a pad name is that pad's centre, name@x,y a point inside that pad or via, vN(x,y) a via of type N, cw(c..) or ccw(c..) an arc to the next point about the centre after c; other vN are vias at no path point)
+3V3: 3V3.1 C4.2 C5.2 C25.2 C26.2 E9.1 E9.2 E38.1 J6.6 J6.12 J7.6 J7.12 J10.1 J12.2 J12.4 J14.8 POT1.1 R1.2 R3.1 R20.2 R21.1 R22.2 R23.2 R24.2 U3.1 U3.2 | length 13374.7
  Top Layer w10: J12.4@3342,3535 3415,3535 3459,3491 3459,3380 3414,3335 J12.2@3342,3335 3291,3284 3291,2439.5 C25.2@3134.5,2283 J7.6@3134.49,2167 J7.12@3134.49,2067 3316.49,1885 4887,1885 4945.51,1943.51 J6.12@4945.51,2067 J6.6@4945.51,2167 ; R3.1@4368,6159.98 4507,6298.98 4507,6412 4583,6488 v1(4631,6488) 4631,6623.5 v1(4631.5,6624) 4631.5,6643.5 4663,6675 4700,6675 4712.5,6687.5 C5.2@4712.5,6712 C4.2@4712.5,6781 4712.5,6887 4712.7,6887.2 U3.2@4621.12,6887.2 U3.1@4621.12,6861.61 ; R22.2@4671.5,2088 R23.2@4671.5,2155 ; C26.2@4945.51,2283 J6.6@4945.51,2167 ; C26.2@4946.5,2283 4946.5,2348.01 4954.5,2356 3V3.1@5722,2356 ; v1(5181,6361) 5207,6361 5208.5,6362.5 R20.2@5238,6362.5 5238,6230 5274,6194 5274,5614.87 5277,5611.87 5277,5596.13 5265.87,5585 5260,5585 5260,5355.87 5264,5351.87 5264,5336.13 5260,5332.13 5260,5180 5114,5034 5055,5034 5055,4934 5180,4934 5260,4854 5260,4616.13 5288,4588.13 5288,4141 J14.8@5242,4095 5153,4006 5153,3304.63 5152,3303.63 5152,2961 5064,2873 4600,2873 4583,2856 4583,2702.73 POT1.1@4608.72,2677.01 4608.72,2590.28 4671.5,2527.5 R21.1@4671.5,2287 R24.2@4671.5,2221 R23.2@4671.5,2155 ; R23.2@4671.5,2155 4830,2155 4842,2167 J6.6@4945.51,2167
  Signal Layer 1 w10: J10.1@3432,6969 3504,6969 3650.5,6822.5 v1(4713.5,6822.5)
  Bottom Layer w10: v1(4631,6488) 5054,6488 v1(5181,6361) ; 4994.56,5035 5027,5035
+3V3JLOB: C28.2 C32.2 C34.2 E38.2 J17.1 R13.2 R16.1 R27.1 U2.8 U2.14 U2.15 U2.31 U2.35 U2.38 | length 3790.7
  Top Layer w10: R16.1@3550,6663.5 R27.1@3668,6663.5 3702.5,6663.5 3722,6644 3722,6621 3742.5,6600.5 C28.2@3787,6600.5 ; U2.31@3660.42,6199.81 3660.42,6177.58 3696,6142 3751,6142 ; U2.35@3739.16,6199.81 3739.16,6153.84 3751,6142 ; U2.15@3758.84,6426.19 U2.14@3778.53,6426.19 3778.53,6552.53 3787,6561 C28.2@3787,6600.5 ; U2.38@3798.21,6199.81 3798.21,6177.79 3834,6142 ; v1@3821.5,6600.5 C28.2@3787,6600.5 ; U2.8@3862.19,6362.21 4082.78,6362.21 4109.5,6335.5 C32.2@4143,6335.5 v1@4198.5,6335.5 ; v1(3863,5999) 3841.5,6020.5 C34.2@3841.5,6095 3841.5,6134.5 3834,6142 ; J17.1@4580,6153 4685.5,6153 R13.2@4723,6190.5 4742.5,6190.5 4762,6210 4762,6556.5 v1(4694.5,6624) ; 3751,6142 3834,6142
  Signal Layer 1 w10: v1(3828,6601) 3931,6601 v1(4196.87,6335.13)
  Signal Layer 2 w10: v1(3863,5999) 4542,5999 4580,6037 J17.1@4580,6153 4379,6153 v1(4196.87,6335.13)
+5V: 5V.1 C1.2 C2.2 C36.1 C37.2 D2.K D3.K J12.5 U3.5 U3.7 U3.8 U4.5 | length 7677.6
  Top Layer w10: D2.K@4241,6938.8 D3.K@4341,6938.8 4381,6938.8 4381.42,6938.39 4438,6938.39 ; v1(4388,6712) C1.2@4487.5,6712 C2.2@4487.5,6781 4487.5,6827.5 4510.88,6850.88 U3.8@4510.88,6861.61 U3.7@4510.88,6887.2 4467.8,6887.2 4438,6917 4438,6938.39 ; U3.5@4510.88,6938.39 4438,6938.39 ; v1(5414,6652) 5424.4,6662.4 U4.5@5424.4,6693.76 5493.75,6693.76 C37.2@5494,6693.5 5587.5,6693.5 C36.1@5589,6694.02
  Bottom Layer w10: 5V.1@2882,2356 2882,3567 2901,3586 3293,3586 J12.5@3342,3635 3296,3681 3296,3954.05 3340,3998.05 3340,5793.87 3323,5810.87 3323,6489 3528,6694 3902.87,6694 3920.87,6712 v1(4388,6712) 5354,6712 v1(5414,6652)
+5V_FS: C38.2 C39.1 J16.1 U4.1 | length 1501.7
  Top Layer w10: U4.1@5424.4,6788.24 5424.5,6788.34 C38.2@5424.5,6845 5424.5,6932.5 5479,6987 C39.1@5582.7,6987
  Signal Layer 2 w10: J16.1@5013,5929 5151,6067 5151,6661 v1(5422,6932) v1@5425,6935
+5V_JUSB: D2.A E25.2 | length 312.7
  Top Layer w10: v1(4241,6738) D2.A@4241,6789.2
  Signal Layer 1 w10: v1(4060,6686) 4081,6707 4210,6707 v1(4241,6738)
  Bottom Layer w10: E25.2@4060.5,6627 v1@4060.5,6686
+5V_USBFS: D3.A J21.2 | length 1376.2
  Top Layer w10: D3.A@4341,6789.2 4341.2,6789 v1(4394,6789)
  Signal Layer 2 w10: v1(4394,6789) 4595,6588 4923,6588 4973,6538 4973,6196 4951,6174 4951,6006 J21.2@4881,5936
AVCC0: C15.1 E4.1 J2.38 U1.127 | length 2671.5
  Top Layer w10: U1.127@4590.66,4188.26 4768.42,4010.5 C15.1@4789,4010.5 4938.5,4010.5 4976,4048 5037,4048 v1@5049,4036
  Signal Layer 2 w10: v1(4854,3580) 4854,3190 4875,3169 v1(4906,3169) ; v1(5279,4624) 5279,4663 5302,4686 5551,4686 J2.38@5600,4735
  Bottom Layer w10: v1(4854,3580) 4993,3719 4993,3978 v1(5050,4035) 5136,4121 5136,4437 5279,4580 v1(5279,4624) ; v1(4906,3169) E4.1@4906,3227.5
AVSS0: C15.2 E7.2 J2.36 U1.128 | length 3711.5
  Top Layer w10: U1.128@4604.58,4202.18 4652.76,4154 ; 4646.66,4159.66 4732.82,4073.5 C15.2@4789,4073.5 4918.5,4073.5 v1@4940,4095
  Signal Layer 1 w10: v1(4906,3124) 5067,3285 5633.21,3285 5685.21,3337 5685.21,4789 5639.21,4835 J2.36@5600,4835 ; v1(4940,4096) 5077.95,4096 5222.95,4241 5261.05,4241 5313.05,4189 5582,4189 v1@5583,4190
  Signal Layer 2 w10: v1(5582,4190.5) 5684.5,4190.5 v1@5685,4191
  Bottom Layer w10: E7.2@4906,3070.5 v1(4906,3124)
  other v1: 5685,4189.5
GND: C1.1 C2.1 C3.1 C4.1 C5.1 C6.1 C7.1 C8.1 C9.1 C10.2 C11.2 C12.2 C13.2 C14.1 C16.2 C17.2 C18.2 C19.1 C20.1 C21.1 C22.1 C23.1 C24.1 C25.1 C26.1 C27.1 C28.1 C31.1 C32.1 C33.1 C34.1 C36.2 C37.1 C38.1 C39.2 C40.2 C45.2 C46.2 C48.1 C49.1 D1.1 D4.1 E6.1 E7.1 E8.1 E24.1 E35.1 E37.1 GND.1 J1.17 J2.12 J4.36 J6.5 J6.11 J7.5 J7.11 J9.4 J9.5 J9.C1 J9.C2 J9.C3 J9.C4 J10.3 J10.5 J11.5 J11.C1 J11.C2 J11.C3 J11.C4 J12.6 J12.7 J14.7 J17.5 LED1.K LED2.K LED3.K POT1.3 R2.1 R9.1 R18.1 R25.1 RA2.7 RA2.8 S1.2 S1.3 S2.2 S2.3 U1.18 U1.37 U1.48 U1.67 U1.82 U1.91 U1.100 U1.112 U1.122 U1.141 U2.5 U2.11 U2.19 U2.36 U2.37 U3.4 U3.PAD U4.2 U5.2 | length 9266.7
  Top Layer w10: J7.11@3234.49,2067 J7.5@3234.49,2167 3234.49,2246.01 C25.1@3197.5,2283 v1(3237,2283) 3704.1,2283 S1.2@3854.16,2132.94 S1.3@4123.84,2132.95 ; C10.2@3640.5,4665 3751.84,4665 3781.01,4635.83 3781.18,4635.83 U1.67@3822.31,4594.71 v1(3882,4535.01) v1@3882,4534 ; U2.19@3680.1,6426.19 v1@3680.1,6473.1 ; C18.2@3688.5,5205 C46.2@3688.5,5066 3688.5,5046.5 3699.69,5035.31 4009.69,5035.31 4030.5,5014.5 C11.2@4030.5,4999 ; U2.36@3758.84,6199.81 U2.37@3778.53,6199.81 v1@3778.53,6164.47 ; v1(3828,4249.63) U1.82@3877.99,4299.62 3903.07,4324.7 3948.3,4324.7 4028.35,4244.65 4028.35,4203.36 4003.26,4178.27 U1.91@4003.26,4174.34 ; J11.5@3861.82,6894.69 3795.87,6894.69 J11.C2@3790.95,6899.61 3790.95,6944.05 3763.39,6971.61 J11.C4@3763.39,7000 J11.C4@3865.76,7000 J11.C3@3960.24,7000 J11.C3@4062.61,7000 4062.61,6950.61 4035.05,6923.05 J11.C1@4035.05,6899.61 J11.C1@4068.61,6899.61 ; U2.5@3862.19,6303.16 4067.62,6303.16 4098,6272.77 C32.1@4143,6272.5 C31.1@4143,6212.5 ; v1(3895,6713) 3896.38,6711.62 D1.1@3896.38,6657.81 ; v1@4027,4918.95 U1.48@4086.78,4859.18 4215.98,4729.98 4557.02,4729.98 4557.96,4729.04 U1.18@4590.66,4761.74 4684.92,4856 4730.5,4856 C40.2@4736,4861.5 ; LED3.K@4086.53,1962 4123.84,1999.31 S1.3@4123.84,2132.95 ; 4090.47,4011 U1.100@4128.53,4049.07 ; v1(4114,6670) 4114,6642.9 RA2.8@4114.9,6642 ; C17.2@4133.34,5118.84 U1.37@4239.89,5012.29 ; C17.2@4136.5,5111 C17.2@4141.18,5111 ; U1.112@4381.87,3979.47 4441.84,3919.5 C12.2@4537,3919.5 ; U5.2@4456.54,2155 4396.99,2155 C45.2@4330,2088.01 4285.06,2132.95 S1.3@4123.84,2132.95 ; 4488.86,4150.86 U1.122@4521.06,4118.66 C13.2@4656,3983.73 ; C1.1@4550.5,6712 C2.1@4550.5,6781 ; U3.PAD@4566,6900 4566,6826 4550.5,6810.5 C2.1@4550.5,6781 ; C5.1@4649.5,6712 C4.1@4649.5,6781 C2.1@4550.5,6781 ; POT1.3@4699.28,2677.01 4779.01,2677.01 4845.5,2743.5 C6.1@4875,2743.5 5089.5,2743.5 5151,2682 5447,2682 J4.36@5500,2735 ; 4744.66,4424 U1.141@4785.53,4383.13 4888.16,4280.5 C14.1@4920,4280.5 ; R25.1@4845.5,6261 C27.1@4845.5,6340 4845.5,6405.5 4878.5,6438.5 C49.1@4956.61,6438.5 ; C26.1@5009.5,2283 5009.5,2203.02 J6.5@5045.51,2167 J6.11@5045.51,2067
  Signal Layer 1 w10: 4143.5,6899.5 4148,6899.5
  Bottom Layer w10: E24.1@3179.64,6691 3179.64,6916.64 J10.5@3232,6969 ; E35.1@3475,5500.64 3475,5543 3495,5563 3706,5563 3723,5546 E37.1@3723,5509.5 ; E8.1@4806,3007.5 E7.1@4906,3007.5 E6.1@5006,3007.5 ; E6.1@5010,3006.5 5045.51,2970.99 J6.5@5045.51,2167
  other v1: 4484,3877 4025.59,4919.41 3474,5501 3778,6164 3863,6472 3681,6474
JLED: R4.1 U2.27 | length 1007.4
  Top Layer w10: v1(3519,6165) 3519,6258 3544.47,6283.47 U2.27@3635.81,6283.47 ; v1(4236,6163) 4285.98,6163 R4.1@4289,6159.98
  Signal Layer 2 w10: v1(3519,6165) 3537,6183 4216,6183 v1(4236,6163)
JLOB_USB_N: D1.3 J11.2 U2.12 | length 607.3
  Top Layer w10: U2.12@3817.9,6426.19 3817.9,6502.9 3831,6516 3923,6516 3939,6532 3939,6581.76 3948.12,6590.88 ; J11.2@3938.59,6894.69 3938.59,6600.41 3948.12,6590.88 ; D1.3@3975.12,6590.88 3948.12,6590.88
JLOB_USB_P: D1.2 J11.3 U2.13 | length 548.8
  Top Layer w10: U2.13@3798.21,6426.19 3798.21,6517.21 3813.21,6532.21 3857.21,6532.21 3896.38,6571.38 D1.2@3896.38,6590.88 3921.4,6615.91 3921.4,6738.6 3913,6747 J11.3@3913,6894.69
JTAG_RESET#: E36.2 J10.10 U2.28 | length 1940.7
  Top Layer w10: J10.10@3032,6869 3032,6710 3185,6557 3185,6418 3457.27,6145.73 3530,6145.73 3551,6166.73 3551,6241 3573.79,6263.79 U2.28@3635.81,6263.79
  Signal Layer 1 w10: v1@3403,6200 3431,6172 3431,5684.47 3597,5518.47 v1(3597,5510)
  other v1: 3403,6199
NetC3_2: C3.2 U3.6 | length 129.6
  Top Layer w10: v1@4475.5,6975.5 C3.2@4475.5,7013 ; v1@4475.8,6912.8 U3.6@4510.88,6912.8
  Bottom Layer w10: v1(4475,6913) v1(4475,6970)
NetC6_2: C6.2 E31.2 POT1.2 | length 402.8
  Top Layer w10: POT1.2@4650,2777 4679.5,2806.5 C6.2@4875,2806.5
  Bottom Layer w10: E31.2@4650,2867.36 4749.64,2867.36 4763,2854 v1(4763,2807)
NetC17_1: C17.1 E10.1 E11.1 U1.40 | length 883
  Top Layer w10: v1@4073.5,5153.5 4073.5,5095.16 U1.40@4198.13,4970.53
  Signal Layer 1 w10: v1(4074,5155) 4289,5155 v1(4298,5164)
  Signal Layer 2 w10: v1(4298,5164) 4333,5199 v4(4333,5419)
  Bottom Layer w10: v4(4333,5419) E10.1@4333,5460.5 4376.5,5460.5 4385.36,5469.36 E11.1@4439,5469.36
NetC18_1: C18.1 E13.1 | length 101.9
  Top Layer w10: C18.1@3740.5,5205 C18.1@3751.5,5205 v3(3790,5205)
  Bottom Layer w10: v3(3790,5205) E13.1@3842.36,5205
NetC19_2: C19.2 U1.15 | length 1294.8
  Top Layer w10: U1.15@4632.42,4719.98 4679.44,4767 v1(4681,4767) ; C19.2@5012.5,4828 v1@5012.5,4880.5
  Signal Layer 1 w10: v1(4819,4903) 4895,4979 4895,5101 4920.64,5126.64 5196.36,5126.64 5237,5086 5237,4969 5143,4875 v1(5012,4875)
  Signal Layer 2 w10: v1(4681,4767) 4817,4903 v1(4819,4903)
NetC20_2: C20.2 U1.92 | length 472.5
  Top Layer w10: C20.2@3726.5,3885 3726.5,3970.5 v1(3754,3998) ; v1(3968,4111.24) U1.92@4017.18,4160.42
  Bottom Layer w10: v1@3754,4002 3754,4035 3776,4057 3913.76,4057 v1(3968,4111.24)
NetC21_2: C21.2 E14.2 U1.19 X1.1 | length 1101
  Top Layer w10: U1.19@4577.66,4775.66 U1.19@4576.74,4775.66 v1@4646.08,4845 ; X1.1@4726,5251 4771.5,5296.5 C21.2@4868,5296.5 v3(4868,5249)
  Signal Layer 1 w10: v1(4646.08,4845.4) 4661,4860.32 4661,5042 v3(4868,5249) 4964,5345 v1(5082,5345)
  Bottom Layer w10: v1(5082,5345) 5125,5345 E14.2@5126,5344
NetC22_2: C22.2 E15.2 U1.20 X1.2 | length 1336.4
  Top Layer w8: v1(4641,5387) 4641.8,5387.8 X1.2@4726,5387.8 ; C22.2@4868,5482.99 5020.01,5482.99 v1(5060,5443)
  Top Layer w10: U1.20@4562.82,4789.58 v1(4611.24,4838) ; v1(4641,5387) 4641,5464 4688.81,5511.81 4839.18,5511.81 C22.2@4868,5482.99
  Signal Layer 1 w10: v1(4611.24,4838) 4641,4867.76 v1(4641,5387) 4641,5396
  Bottom Layer w10: v1@5060,5444 E15.2@5128,5444
NetC23_2: C23.2 U1.16 X2.1 | length 829
  Top Layer w10: U1.16@4618.5,4733.9 4619.6,4733.9 v1@4687.7,4802 ; C23.2@5030,5295.5 5030,5261 5053.18,5237.82 X2.1@5053.18,5159 v3@5053.18,5092.18
  Signal Layer 1 w10: v1(4687.7,4802.4) 4711.3,4826 4778,4826 4934,4982 4980,4982 5001.5,5003.5 5001.5,5059.5 5035,5093 v3(5053.18,5093)
NetC27_2: C27.2 E19.2 R25.2 R26.1 | length 437.7
  Top Layer w10: v1(4907,6171) 4908.5,6172.5 R25.2@4908.5,6261 ; C27.2@4908.5,6340 R25.2@4908.5,6261 ; R26.1@4974.5,6261 R25.2@4908.5,6261
  Bottom Layer w10: E19.2@4737,6093.5 4829.5,6093.5 v1(4907,6171)
NetC31_2: C31.2 U2.2 | length 351.6
  Top Layer w10: U2.2@3862.19,6244.1 4019.9,6244.1 4039,6225 4039,6171 4060.5,6149.5 C31.2@4143,6149.5
NetC33_2: C33.2 D1.4 E25.1 J11.1 RA2.5 RA2.6 | length 995.1
  Top Layer w10: J11.1@3964.18,6894.69 3964.18,6847.82 3975.5,6836.5 C33.2@4148,6836.5 4148,6789 4159.69,6777.31 RA2.6@4159.69,6642 RA2.5@4184.78,6642 4214,6642 v1(4223,6651) ; D1.4@3975.12,6665.69 4022.31,6665.69 4033,6655 v1(4033,6568)
  Signal Layer 1 w10: v1(4033,6568) 4193,6568 4223,6598 v1(4223,6651)
  Bottom Layer w10: E25.1@3997.5,6627 3997.5,6578 4007.5,6568 v1(4033,6568)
